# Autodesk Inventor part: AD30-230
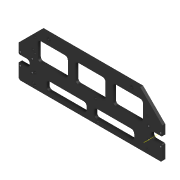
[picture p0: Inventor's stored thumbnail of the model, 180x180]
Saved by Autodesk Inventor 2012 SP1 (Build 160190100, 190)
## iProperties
Shininess: 25.0
Created: 2000-06
Part Number: AD30-230
Project: BONDING PRESS
Material: Aluminum-6061-AHC
Description: BEARING MOUNT PLATE
Document SubType Name: Modeling
Designer: Ron
Density: 2.71 g/cm^3
Density: 2.71
Volumn: 1241.9324484632973
Area: 2480.3750033649326
PropertySet Name: Model Information
Control State: 0
Master: False
Checked Out: False
Title: BEARING MOUNT PLATE
Author: Ron
Revision Number: 01
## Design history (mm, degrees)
node "Extrusion1" dims "d5" = 12.7, "d6" = 0
  sketch "Sketch1"
    geometry: L1 (325, -122.5)-(-325, -122.5); L2 (-325, -122.5)-(-325, 122.5); L3 (-325, 122.5)-(325, 122.5); L4 (325, 122.5)-(325, -122.5); L5 (325, -52.5)-(275, -52.5); L6 (275, -52.5)-(275, -22.5); L7 (275, -22.5)-(325, -22.5); L8 (325, -22.5)-(325, -52.5); L9 (-325, -52.5)-(-275, -52.5); L10 (-275, -52.5)-(-275, -22.5); L11 (-275, -22.5)-(-325, -22.5); L12 (-325, -22.5)-(-325, -52.5); L13 (-325, 122.5)-(325, -122.5); 2 further points
    constraints: 26 end point, 6 parallel, 3 collinear, 3 horizontal, 3 perpendicular, 2 point on line, 1 coincident, 1 midpoint
    dimensions: "d0" = 650 distance of L2.end L3.end; "d1" = 245 distance of L1.end L2.end; "d2" = 30 distance between parallel lines of L7 L5; "d3" = 50 distance between parallel lines of L6 L4; "d4" = 70 distance between parallel lines of L1 L5
node "Fillet1" dims "d7" = 12.7
node "Chamfer1" dims "d8" = 3.175, "d9" = 3.175, "d66" = 45 deg
node "Chamfer2" dims "d10" = 6.35, "d11" = 6.35, "d67" = 45 deg
node "Extrusion2" dims "d27" = 10, "d28" = 0
  sketch "Sketch3"
    geometry: L1 (-318.65, 122.5)-(318.65, 122.5) reference; L2 (-325, -116.15)-(-325, -55.675) reference; L3 (187.5, 103.45)-(-187.5, 103.45); L4 (0, 103.45)-(0, 122.5); C1 r 6.35 at (187.5, 103.45); C2 r 6.35 at (-187.5, 103.45)
    constraints: 4 end point, 2 centre point, 2 midpoint, 2 perpendicular, 1 equal radius, 1 horizontal alignment
    dimensions: "d24" = 12.7 diameter of C1; "d25" = 19.05 distance from line of L1 L3.start; "d26" = 375 distance of L3.end L3.start
workplane "Work Plane1"
workplane "Work Plane2"
node "Extrusion3" dims "d38" = 10, "d39" = 0
  sketch "Sketch4"
    geometry: L1 (325, 116.15)-(325, -19.325) reference; L2 (318.65, 122.5)-(325, 116.15) reference; L3 (-318.65, 122.5)-(318.65, 122.5) reference; L4 (-325, 116.15)-(-318.65, 122.5) reference; L5 (-325, -19.325)-(-325, 116.15) reference; L6 (-318.65, -122.5)-(-325, -116.15) reference; L7 (318.65, -122.5)-(-318.65, -122.5) reference; L8 (325, 22.5)-(225, 122.5); L9 (-325, 22.5)-(-225, 122.5); L10 (325, 22.5)-(-325, 22.5); L11 (237.5, -7.5)-(102.5, -7.5); L12 (102.5, -7.5)-(102.5, 77.5); L13 (102.5, 77.5)-(237.5, 77.5); L14 (237.5, 77.5)-(237.5, -7.5); L15 (67.5, 77.5)-(-67.5, 77.5); L16 (-67.5, 77.5)-(-67.5, -7.5); L17 (-67.5, -7.5)-(67.5, -7.5); L18 (67.5, -7.5)-(67.5, 77.5); L19 (-102.5, -7.5)-(-237.5, -7.5); L20 (-237.5, -7.5)-(-237.5, 77.5); L21 (-237.5, 77.5)-(-102.5, 77.5); L22 (-102.5, 77.5)-(-102.5, -7.5); L23 (102.5, 77.5)-(67.5, 77.5); L24 (-67.5, 77.5)-(-102.5, 77.5); L25 (237.5, 77.5)-(325, 77.5); L26 (-237.5, 77.5)-(-325, 77.5); L27 (-197.5, -60.5)-(-17.5, -60.5); L28 (-17.5, -60.5)-(-17.5, -100.5); L29 (-17.5, -100.5)-(-197.5, -100.5); L30 (-197.5, -100.5)-(-197.5, -60.5); L31 (17.5, -60.5)-(197.5, -60.5); L32 (197.5, -60.5)-(197.5, -100.5); L33 (197.5, -100.5)-(17.5, -100.5); L34 (17.5, -100.5)-(17.5, -60.5); L35 (-17.5, -100.5)-(17.5, -100.5); L36 (0, -100.5)-(0, -122.5)
    constraints: 58 end point, 12 perpendicular, 11 parallel, 10 collinear, 6 point on line, 5 horizontal, 2 midpoint
    dimensions: "d29" = 100 distance from line of L3 L8.start; "d30" = 135 distance of L15.start L15.end; "d31" = 85 distance of L19.end L20.end; "d32" = 45 distance between parallel lines of L3 L21; "d33" = 35 distance between parallel lines of L34 L28; "d34" = 35 distance between parallel lines of L16 L22; "d35" = 22 distance between parallel lines of L7 L33; "d36" = 40 distance between parallel lines of L31 L33; "d37" = 180 distance of L28.end L29.end
node "Fillet2" dims "d40" = 12.7
node "Extrusion4" dims "d44" = 10, "d45" = 0
  sketch "Sketch5"
    geometry: L1 (318.65, -122.5)-(-318.65, -122.5) reference; L2 (-484.656, -5.396)-(-484.656, -285.396) reference; L3 (30.079, -5.396)-(30.079, -285.396) reference; C1 r 3.175 at (-487.831, 67.5); C2 r 3.175 at (-487.831, -107.9); C3 r 3.175 at (33.254, -107.9); C4 r 3.175 at (33.254, 67.5)
    constraints: 4 centre point, 4 tangent, 3 equal radius, 2 horizontal alignment
    dimensions: "d41" = 6.35 diameter of C1; "d42" = 14.6 distance from line of L1 C2.centre; "d43" = 190 distance from line of L1 C1.centre
node "Hole2" dims "d46" = 4.2, "d47" = 8, "d48" = 4.5, "d49" = 60 deg, "d50" = 8, "d51" = 118 deg
  sketch "Sketch6"
    geometry: C1 r 1.621 at (-478.656, -210.396) reference; C2 r 1.621 at (-478.656, -160.396) reference; C3 r 1.621 at (-478.656, -85.396) reference; C4 r 1.621 at (-478.656, -20.396) reference; C5 r 1.621 at (24.079, -20.396) reference; C6 r 1.621 at (24.079, -85.396) reference; C7 r 1.621 at (24.079, -160.396) reference; C8 r 1.621 at (24.079, -210.396) reference; 8 further points
    constraints: 8 coincident
node "Hole4" dims "d58" = 3.242, "d59" = 4, "d60" = 2, "d61" = 60 deg, "d62" = 8, "d63" = 118 deg, "d65" = 6
  sketch "Sketch8"
    geometry: L1 (34.225, -116.15)-(43.75, -116.15); L2 (43.75, -116.15)-(53.275, -116.15); L3 (318.65, -122.5)-(-318.65, -122.5) reference; L4 (0, 0)-(0, -122.5)
    constraints: 6 end point, 2 collinear, 1 horizontal alignment, 1 midpoint
    dimensions: "d70" = 19.05 distance of L1.start L2.end; "d93" = 6.35 distance between parallel lines of L3 L2; "d94" = 43.75 distance from line of L1.end L4
sketch "Sketch9"
  geometry: L1 (318.65, -122.5)-(-318.65, -122.5) reference; L2 (54.8, -7.5)-(-54.8, -7.5) reference; L3 (-250, -122.5)-(-250, -107.5); L4 (-250, -107.5)-(-250, -57.5); L5 (-250, -57.5)-(-250, 17.5); L6 (-250, 17.5)-(-250, 82.5); 1 further point
  constraints: 8 end point, 3 collinear, 1 midpoint, 1 perpendicular, 1 point on line
  dimensions: "d71" = 15 distance of L3.start L3.end; "d72" = 50 distance of L3.end L4.end; "d73" = 75 distance of L4.end L5.end; "d74" = 65 distance of L5.end L6.end; "d75" = 250 distance from line of L3 point (0, -122.5)
hole "Hole5" sketch "Sketch9" at (-250, -107.5), (-250, -57.5), (-250, 17.5), (-250, 82.5) diameter "d76" = 4.5; stored, may be unused: countersink angle "d80" = 90 deg, drill point angle "d82" = 118 deg; dims "d77" = 6, "d78" = 8, "d79" = 4, "d81" = 8
sketch "Sketch10"
  geometry: L1 (256, 97.5)-(256, -182.5) reference; L2 (259.175, 97.5)-(259.175, -182.5); L3 (287.7, -39.8)-(287.7, -35.2); L4 (259.175, -102.5)-(287.7, -37.5); L5 (287.7, -37.5)-(259.175, 27.5); C1 r 4 at (250, 17.5) reference; A1 r 12.7 centre (287.7, -39.8) between (275, -39.8) and (287.7, -52.5) reference; A2 r 12.7 centre (287.7, -35.2) between (287.7, -22.5) and (275, -35.2) reference
  constraints: 10 end point, 2 parallel, 2 point on line, 1 equal length, 1 midpoint, 1 vertical, 2 other
  dimensions: "d83" = 3.175 distance between parallel lines of L2 L1; "d84" = 120 vertical distance of C1.centre L4.start
hole "Hole6" sketch "Sketch10" at (259.175, 27.5), (259.175, -102.5) diameter "d85" = 6.35; stored, may be unused: countersink angle "d89" = 90 deg, drill point angle "d91" = 118 deg; dims "d86" = 6, "d87" = 4, "d88" = 2, "d90" = 8
mirror "Mirror1"
sketch "Sketch11"
  geometry: L1 (-225, 122.5)-(-325, 22.5) reference; L2 (-325, -19.325)-(-325, 22.5) reference; L3 (-321.825, -22.5)-(-325, -19.325) reference; L4 (-321.825, -22.5)-(-287.7, -22.5) reference; L5 (-275, -35.2)-(-275, -39.8) reference; L6 (-287.7, -52.5)-(-321.825, -52.5) reference; L7 (-325, -55.675)-(-321.825, -52.5) reference; L8 (-325, -116.15)-(-325, -55.675) reference; L9 (-318.65, -122.5)-(-325, -116.15) reference; L10 (318.65, -122.5)-(-318.65, -122.5) reference; L11 (325, -116.15)-(318.65, -122.5) reference; L12 (325, -55.675)-(325, -116.15) reference; L13 (321.825, -52.5)-(325, -55.675) reference; L14 (321.825, -52.5)-(287.7, -52.5) reference; L15 (275, -39.8)-(275, -35.2) reference; L16 (287.7, -22.5)-(321.825, -22.5) reference; L17 (325, -19.325)-(321.825, -22.5) reference; L18 (325, 22.5)-(325, -19.325) reference; L19 (325, 22.5)-(225, 122.5) reference; L20 (-225, 122.5)-(225, 122.5) reference; L21 (-224.8, 77.5)-(-115.2, 77.5) reference; L22 (-102.5, 64.8)-(-102.5, 5.2) reference; L23 (-115.2, -7.5)-(-224.8, -7.5) reference; L24 (-237.5, 5.2)-(-237.5, 64.8) reference; L25 (115.2, 77.5)-(224.8, 77.5) reference; L26 (237.5, 64.8)-(237.5, 5.2) reference; L27 (224.8, -7.5)-(115.2, -7.5) reference; L28 (102.5, 5.2)-(102.5, 64.8) reference; L29 (-30.2, -100.5)-(-184.8, -100.5) reference; L30 (-197.5, -87.8)-(-197.5, -73.2) reference; L31 (-184.8, -60.5)-(-30.2, -60.5) reference; L32 (-17.5, -73.2)-(-17.5, -87.8) reference; L33 (184.8, -100.5)-(30.2, -100.5) reference; L34 (17.5, -87.8)-(17.5, -73.2) reference; L35 (30.2, -60.5)-(184.8, -60.5) reference; L36 (197.5, -73.2)-(197.5, -87.8) reference; L37 (-67.5, 5.2)-(-67.5, 64.8) reference; L38 (-54.8, 77.5)-(54.8, 77.5) reference; L39 (67.5, 64.8)-(67.5, 5.2) reference; L40 (54.8, -7.5)-(-54.8, -7.5) reference; L41 (-275, -37.5)-(275, -37.5); C1 r 3.175 at (259.175, 27.5) reference; C2 r 3.175 at (259.175, -102.5) reference; C3 r 3.175 at (-259.175, 27.5) reference; C4 r 3.175 at (-259.175, -102.5) reference; C5 r 4 at (-250, 17.5) reference; C6 r 4 at (-250, -107.5) reference; C7 r 4 at (-250, -57.5) reference; C8 r 4 at (-250, 82.5) reference; C9 r 1.621 at (34.225, -116.15) reference; C10 r 1.621 at (53.275, -116.15) reference; C11 r 4 at (24.079, -20.396) reference; C12 r 3.175 at (33.254, -107.9) reference; C13 r 3.3 at (317.062, -64.488) reference; C14 r 3.3 at (263.087, -10.512) reference; C15 r 3.3 at (-317.062, -64.488) reference; C16 r 3.3 at (-263.087, -10.512) reference; C17 r 3.3 at (-317.062, -10.512) reference; C18 r 3.3 at (-263.087, -64.488) reference; C19 r 3.3 at (317.062, -10.512) reference; C20 r 3.3 at (263.087, -64.488) reference; C21 r 6.35 at (187.5, 103.45) reference; C22 r 6.35 at (-187.5, 103.45) reference; A1 r 12.7 centre (-287.7, -35.2) between (-275, -35.2) and (-287.7, -22.5) reference; A2 r 12.7 centre (-287.7, -39.8) between (-287.7, -52.5) and (-275, -39.8) reference; A3 r 12.7 centre (287.7, -39.8) between (275, -39.8) and (287.7, -52.5) reference; A4 r 12.7 centre (287.7, -35.2) between (287.7, -22.5) and (275, -35.2) reference; A5 r 12.7 centre (-115.2, 64.8) between (-102.5, 64.8) and (-115.2, 77.5) reference; A6 r 12.7 centre (-115.2, 5.2) between (-115.2, -7.5) and (-102.5, 5.2) reference; A7 r 12.7 centre (-224.8, 5.2) between (-237.5, 5.2) and (-224.8, -7.5) reference; A8 r 12.7 centre (-224.8, 64.8) between (-224.8, 77.5) and (-237.5, 64.8) reference; A9 r 12.7 centre (224.8, 64.8) between (237.5, 64.8) and (224.8, 77.5) reference; A10 r 12.7 centre (224.8, 5.2) between (224.8, -7.5) and (237.5, 5.2) reference; A11 r 12.7 centre (115.2, 5.2) between (102.5, 5.2) and (115.2, -7.5) reference; A12 r 12.7 centre (115.2, 64.8) between (115.2, 77.5) and (102.5, 64.8) reference; A13 r 12.7 centre (-184.8, -87.8) between (-197.5, -87.8) and (-184.8, -100.5) reference; A14 r 12.7 centre (-184.8, -73.2) between (-184.8, -60.5) and (-197.5, -73.2) reference; A15 r 12.7 centre (-30.2, -73.2) between (-17.5, -73.2) and (-30.2, -60.5) reference; A16 r 12.7 centre (-30.2, -87.8) between (-30.2, -100.5) and (-17.5, -87.8) reference; A17 r 12.7 centre (30.2, -87.8) between (17.5, -87.8) and (30.2, -100.5) reference; A18 r 12.7 centre (30.2, -73.2) between (30.2, -60.5) and (17.5, -73.2) reference; A19 r 12.7 centre (184.8, -73.2) between (197.5, -73.2) and (184.8, -60.5) reference; A20 r 12.7 centre (184.8, -87.8) between (184.8, -100.5) and (197.5, -87.8) reference; A21 r 12.7 centre (-54.8, 64.8) between (-54.8, 77.5) and (-67.5, 64.8) reference; A22 r 12.7 centre (54.8, 64.8) between (67.5, 64.8) and (54.8, 77.5) reference; A23 r 12.7 centre (54.8, 5.2) between (54.8, -7.5) and (67.5, 5.2) reference; A24 r 12.7 centre (-54.8, 5.2) between (-67.5, 5.2) and (-54.8, -7.5) reference
  constraints: 2 end point, 2 midpoint
workplane "Work Plane3"
sketch "Sketch12"
  geometry: L1 (-325, -19.325)-(-325, 22.5) reference; L2 (-275, -35.2)-(-275, -39.8) reference; L3 (102.5, 5.2)-(102.5, 64.8) reference; L4 (-275, -37.5)-(-290, -37.5); 2 further points
  constraints: 2 end point, 1 midpoint, 1 perpendicular
  dimensions: "d95" = 27 horizontal distance of point (-317, -10.5) L4.end (= d112); "d111" = 35 distance from line of L4.end L1; "d112" = 27 horizontal distance of L4.end point (-317, -10.5)
hole "Hole7" sketch "Sketch12" at (-290, -37.5), (-317, -10.5) diameter "d97" = 6.6; stored, may be unused: countersink angle "d101" = 90 deg, drill point angle "d103" = 118 deg; dims "d98" = 6, "d99" = 14, "d100" = 1, "d102" = 8
pattern_linear "Rectangular Pattern1" dims "d106" = 54, "d109" = 54
mirror "Mirror2"
node "Guide Axis"
body "Solid1"
